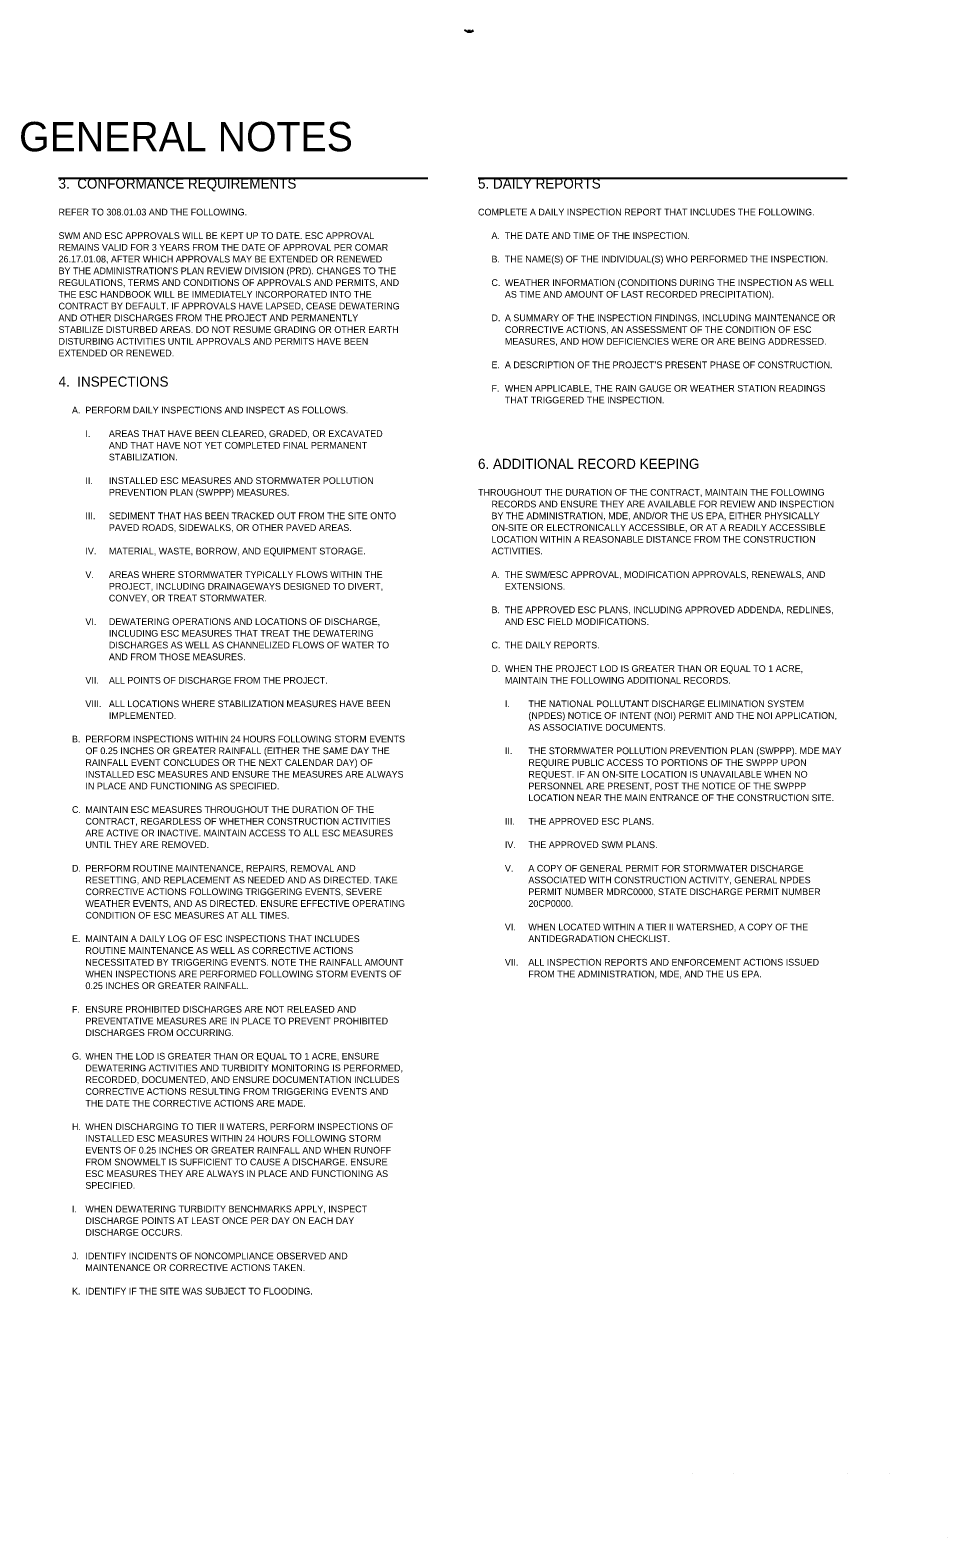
# Model space of a CAD drawing. Extents: x 1.3 to 34, y 0 to 22.5.
# Drawn here: x 20.33 to 34, y 0 to 22.46 of the extents above; entities that cross this region are included whole.
import ezdxf

# ---------------------------------------------------------------- set-up
doc = ezdxf.new("R2010")
doc.units = 0
for name, color, linetype in [('ANNO-NOTE', 7, 'Continuous'), ('TTLB-TEXT', 7, 'Continuous'), ('USER-LINE', 7, 'Continuous')]:
    doc.layers.add(name, color=color, linetype=linetype)

msp = doc.modelspace()

# ---------------------------------------------------------------- linework, layer by layer
at = {"layer": 'ANNO-NOTE'}
for p, q in [((26.891, 22.441), (26.93, 22.461)), ((26.891, 22.441), (26.93, 22.461)), ((26.891, 22.441), (26.93, 22.461)), ((26.843, 22.436), (26.799, 22.459)), ((26.843, 22.436), (26.799, 22.459)), ((26.843, 22.436), (26.799, 22.459)), ((26.843, 22.436), (26.894, 22.436)), ((26.843, 22.436), (26.894, 22.436)), ((26.843, 22.436), (26.894, 22.436)), ((26.844, 22.438), (26.892, 22.438)), ((26.844, 22.438), (26.892, 22.438)), ((26.844, 22.438), (26.892, 22.438)), ((26.845, 22.441), (26.891, 22.441)), ((26.845, 22.441), (26.891, 22.441)), ((26.845, 22.441), (26.891, 22.441)), ((26.847, 22.451), (26.89, 22.451)), ((26.847, 22.451), (26.89, 22.451)), ((26.847, 22.451), (26.89, 22.451)), ((26.847, 22.443), (26.89, 22.443)), ((26.847, 22.443), (26.89, 22.443)), ((26.847, 22.443), (26.89, 22.443)), ((26.848, 22.454), (26.888, 22.454)), ((26.848, 22.454), (26.888, 22.454)), ((26.848, 22.454), (26.888, 22.454)), ((26.848, 22.445), (26.889, 22.446)), ((26.848, 22.445), (26.889, 22.446)), ((26.848, 22.445), (26.889, 22.446)), ((26.892, 22.438), (26.931, 22.458)), ((26.892, 22.438), (26.931, 22.458)), ((26.892, 22.438), (26.931, 22.458)), ((26.894, 22.436), (26.932, 22.456)), ((26.894, 22.436), (26.932, 22.456)), ((26.894, 22.436), (26.932, 22.456))]:
    msp.add_line(p, q, dxfattribs=at)
at = {"layer": 'TTLB-TEXT'}
for p, q in [((30.191, 0.958), (30.191, 0.958)), ((30.807, 0.958), (30.807, 0.958)), ((32.512, 0.958), (32.512, 0.958)), ((33.128, 0.958), (33.128, 0.958))]:
    msp.add_line(p, q, dxfattribs=at)
at = {"layer": 'USER-LINE'}
for p, q in [((26.25, 20.25), (20.75, 20.25)), ((32.5, 20.25), (27, 20.25)), ((34, 0), (34, 0))]:
    msp.add_line(p, q, dxfattribs=at)

# ---------------------------------------------------------------- texts
at = {"layer": 'ANNO-NOTE'}
for s, height, p in [('EROSION AND SEDIMENT CONTROL (ESC) - GENERAL NOTES', 0.4375, (7.583, 20.656)), ('3.  CONFORMANCE REQUIREMENTS', 0.15, (20.75, 20.1)), ('5. DAILY REPORTS', 0.15, (27, 20.1)), ('REFER TO 308.01.03 AND THE FOLLOWING.', 0.1, (20.75, 19.7)), ('COMPLETE A DAILY INSPECTION REPORT THAT INCLUDES THE FOLLOWING.', 0.1, (27, 19.7)), ('SWM AND ESC APPROVALS WILL BE KEPT UP TO DATE. ESC APPROVAL ', 0.1, (20.75, 19.35)), ('A.', 0.1, (27.2, 19.35)), ('THE DATE AND TIME OF THE INSPECTION.', 0.1, (27.4, 19.35)), ('26.17.01.08, AFTER WHICH APPROVALS MAY BE EXTENDED OR RENEWED ', 0.1, (20.75, 19)), ('REMAINS VALID FOR 3 YEARS FROM THE DATE OF APPROVAL PER COMAR ', 0.1, (20.75, 19.175)), ('B.', 0.1, (27.2, 19)), ('THE NAME(S) OF THE INDIVIDUAL(S) WHO PERFORMED THE INSPECTION.', 0.1, (27.4, 19)), ('BY THE ADMINISTRATION’S PLAN REVIEW DIVISION (PRD). CHANGES TO THE ', 0.1, (20.75, 18.825)), ('REGULATIONS, TERMS AND CONDITIONS OF APPROVALS AND PERMITS, AND ', 0.1, (20.75, 18.65)), ('C.', 0.1, (27.2, 18.65)), ('WEATHER INFORMATION (CONDITIONS DURING THE INSPECTION AS WELL ', 0.1, (27.4, 18.65)), ('THE ESC HANDBOOK WILL BE IMMEDIATELY INCORPORATED INTO THE ', 0.1, (20.75, 18.475)), ('AS TIME AND AMOUNT OF LAST RECORDED PRECIPITATION).', 0.1, (27.4, 18.475)), ('AND OTHER DISCHARGES FROM THE PROJECT AND PERMANENTLY ', 0.1, (20.75, 18.125)), ('CONTRACT BY DEFAULT. IF APPROVALS HAVE LAPSED, CEASE DEWATERING ', 0.1, (20.75, 18.3)), ('D.', 0.1, (27.2, 18.125)), ('A SUMMARY OF THE INSPECTION FINDINGS, INCLUDING MAINTENANCE OR ', 0.1, (27.4, 18.125)), ('STABILIZE DISTURBED AREAS. DO NOT RESUME GRADING OR OTHER EARTH ', 0.1, (20.75, 17.95)), ('CORRECTIVE ACTIONS, AN ASSESSMENT OF THE CONDITION OF ESC ', 0.1, (27.4, 17.95)), ('DISTURBING ACTIVITIES UNTIL APPROVALS AND PERMITS HAVE BEEN ', 0.1, (20.75, 17.775)), ('MEASURES, AND HOW DEFICIENCIES WERE OR ARE BEING ADDRESSED.', 0.1, (27.4, 17.775)), ('EXTENDED OR RENEWED.', 0.1, (20.75, 17.6)), ('E.', 0.1, (27.2, 17.425)), ('A DESCRIPTION OF THE PROJECT’S PRESENT PHASE OF CONSTRUCTION.', 0.1, (27.4, 17.425)), ('4.  INSPECTIONS', 0.15, (20.75, 17.15)), ('F.', 0.1, (27.2, 17.075)), ('WHEN APPLICABLE, THE RAIN GAUGE OR WEATHER STATION READINGS ', 0.1, (27.4, 17.075)), ('A.', 0.1, (20.95, 16.75)), ('PERFORM DAILY INSPECTIONS AND INSPECT AS FOLLOWS.', 0.1, (21.15, 16.75)), ('THAT TRIGGERED THE INSPECTION.', 0.1, (27.4, 16.9)), ('I.', 0.1, (21.15, 16.4)), ('AREAS THAT HAVE BEEN CLEARED, GRADED, OR EXCAVATED ', 0.1, (21.5, 16.4)), ('AND THAT HAVE NOT YET COMPLETED FINAL PERMANENT ', 0.1, (21.5, 16.225)), ('STABILIZATION.', 0.1, (21.5, 16.05)), ('6. ADDITIONAL RECORD KEEPING', 0.15, (27, 15.925)), ('II.', 0.1, (21.15, 15.7)), ('INSTALLED ESC MEASURES AND STORMWATER POLLUTION ', 0.1, (21.5, 15.7)), ('PREVENTION PLAN (SWPPP) MEASURES.', 0.1, (21.5, 15.525)), ('THROUGHOUT THE DURATION OF THE CONTRACT, MAINTAIN THE FOLLOWING ', 0.1, (27, 15.525)), ('III.', 0.1, (21.15, 15.175)), ('SEDIMENT THAT HAS BEEN TRACKED OUT FROM THE SITE ONTO ', 0.1, (21.5, 15.175)), ('RECORDS AND ENSURE THEY ARE AVAILABLE FOR REVIEW AND INSPECTION ', 0.1, (27.2, 15.35)), ('BY THE ADMINISTRATION, MDE, AND/OR THE US EPA, EITHER PHYSICALLY ', 0.1, (27.2, 15.175)), ('PAVED ROADS, SIDEWALKS, OR OTHER PAVED AREAS.', 0.1, (21.5, 15)), ('ON-SITE OR ELECTRONICALLY ACCESSIBLE, OR AT A READILY ACCESSIBLE ', 0.1, (27.2, 15)), ('LOCATION WITHIN A REASONABLE DISTANCE FROM THE CONSTRUCTION ', 0.1, (27.2, 14.825)), ('IV.', 0.1, (21.15, 14.65)), ('MATERIAL, WASTE, BORROW, AND EQUIPMENT STORAGE.', 0.1, (21.5, 14.65)), ('ACTIVITIES.', 0.1, (27.2, 14.65)), ('V.', 0.1, (21.15, 14.3)), ('AREAS WHERE STORMWATER TYPICALLY FLOWS WITHIN THE ', 0.1, (21.5, 14.3)), ('A.', 0.1, (27.2, 14.3)), ('THE SWM/ESC APPROVAL, MODIFICATION APPROVALS, RENEWALS, AND ', 0.1, (27.4, 14.3)), ('PROJECT, INCLUDING DRAINAGEWAYS DESIGNED TO DIVERT, ', 0.1, (21.5, 14.125)), ('EXTENSIONS.', 0.1, (27.4, 14.125)), ('CONVEY, OR TREAT STORMWATER.', 0.1, (21.5, 13.95)), ('DEWATERING OPERATIONS AND LOCATIONS OF DISCHARGE, ', 0.1, (21.5, 13.6)), ('B.', 0.1, (27.2, 13.775)), ('AND ESC FIELD MODIFICATIONS.', 0.1, (27.4, 13.6)), ('THE APPROVED ESC PLANS, INCLUDING APPROVED ADDENDA, REDLINES, ', 0.1, (27.4, 13.775)), ('VI.', 0.1, (21.15, 13.6)), ('INCLUDING ESC MEASURES THAT TREAT THE DEWATERING ', 0.1, (21.5, 13.425)), ('DISCHARGES AS WELL AS CHANNELIZED FLOWS OF WATER TO ', 0.1, (21.5, 13.25)), ('C.', 0.1, (27.2, 13.25)), ('THE DAILY REPORTS.', 0.1, (27.4, 13.25)), ('AND FROM THOSE MEASURES.', 0.1, (21.5, 13.075)), ('VII.', 0.1, (21.15, 12.725)), ('ALL POINTS OF DISCHARGE FROM THE PROJECT.', 0.1, (21.5, 12.725)), ('D.', 0.1, (27.2, 12.9)), ('WHEN THE PROJECT LOD IS GREATER THAN OR EQUAL TO 1 ACRE, ', 0.1, (27.4, 12.9)), ('MAINTAIN THE FOLLOWING ADDITIONAL RECORDS.', 0.1, (27.4, 12.725)), ('VIII.', 0.1, (21.15, 12.375)), ('ALL LOCATIONS WHERE STABILIZATION MEASURES HAVE BEEN ', 0.1, (21.5, 12.375)), ('I.', 0.1, (27.4, 12.375)), ('THE NATIONAL POLLUTANT DISCHARGE ELIMINATION SYSTEM ', 0.1, (27.75, 12.375)), ('IMPLEMENTED.', 0.1, (21.5, 12.2)), ('(NPDES) NOTICE OF INTENT (NOI) PERMIT AND THE NOI APPLICATION, ', 0.1, (27.75, 12.2)), ('B.', 0.1, (20.95, 11.85)), ('PERFORM INSPECTIONS WITHIN 24 HOURS FOLLOWING STORM EVENTS ', 0.1, (21.15, 11.85)), ('AS ASSOCIATIVE DOCUMENTS.', 0.1, (27.75, 12.025)), ('OF 0.25 INCHES OR GREATER RAINFALL (EITHER THE SAME DAY THE ', 0.1, (21.15, 11.675)), ('II.', 0.1, (27.4, 11.675)), ('THE STORMWATER POLLUTION PREVENTION PLAN (SWPPP). MDE MAY ', 0.1, (27.75, 11.675)), ('RAINFALL EVENT CONCLUDES OR THE NEXT CALENDAR DAY) OF ', 0.1, (21.15, 11.5)), ('REQUIRE PUBLIC ACCESS TO PORTIONS OF THE SWPPP UPON ', 0.1, (27.75, 11.5)), ('INSTALLED ESC MEASURES AND ENSURE THE MEASURES ARE ALWAYS ', 0.1, (21.15, 11.325)), ('IN PLACE AND FUNCTIONING AS SPECIFIED.', 0.1, (21.15, 11.15)), ('REQUEST. IF AN ON-SITE LOCATION IS UNAVAILABLE WHEN NO ', 0.1, (27.75, 11.325)), ('PERSONNEL ARE PRESENT, POST THE NOTICE OF THE SWPPP ', 0.1, (27.75, 11.15)), ('LOCATION NEAR THE MAIN ENTRANCE OF THE CONSTRUCTION SITE.', 0.1, (27.75, 10.975)), ('C.', 0.1, (20.95, 10.8)), ('MAINTAIN ESC MEASURES THROUGHOUT THE DURATION OF THE ', 0.1, (21.15, 10.8)), ('CONTRACT, REGARDLESS OF WHETHER CONSTRUCTION ACTIVITIES ', 0.1, (21.15, 10.625)), ('III.', 0.1, (27.4, 10.625)), ('THE APPROVED ESC PLANS.', 0.1, (27.75, 10.625)), ('ARE ACTIVE OR INACTIVE. MAINTAIN ACCESS TO ALL ESC MEASURES ', 0.1, (21.15, 10.45)), ('UNTIL THEY ARE REMOVED.', 0.1, (21.15, 10.275)), ('IV.', 0.1, (27.4, 10.275)), ('THE APPROVED SWM PLANS.', 0.1, (27.75, 10.275)), ('D.', 0.1, (20.95, 9.925)), ('PERFORM ROUTINE MAINTENANCE, REPAIRS, REMOVAL AND ', 0.1, (21.15, 9.925)), ('V.', 0.1, (27.4, 9.925)), ('A COPY OF GENERAL PERMIT FOR STORMWATER DISCHARGE ', 0.1, (27.75, 9.925)), ('CORRECTIVE ACTIONS FOLLOWING TRIGGERING EVENTS, SEVERE ', 0.1, (21.15, 9.575)), ('RESETTING, AND REPLACEMENT AS NEEDED AND AS DIRECTED. TAKE ', 0.1, (21.15, 9.75)), ('ASSOCIATED WITH CONSTRUCTION ACTIVITY, GENERAL NPDES ', 0.1, (27.75, 9.75)), ('PERMIT NUMBER MDRC0000, STATE DISCHARGE PERMIT NUMBER ', 0.1, (27.75, 9.575)), ('WEATHER EVENTS, AND AS DIRECTED. ENSURE EFFECTIVE OPERATING ', 0.1, (21.15, 9.4)), ('20CP0000.', 0.1, (27.75, 9.4)), ('CONDITION OF ESC MEASURES AT ALL TIMES.', 0.1, (21.15, 9.225)), ('VI.', 0.1, (27.4, 9.05)), ('WHEN LOCATED WITHIN A TIER II WATERSHED, A COPY OF THE ', 0.1, (27.75, 9.05)), ('E.', 0.1, (20.95, 8.875)), ('MAINTAIN A DAILY LOG OF ESC INSPECTIONS THAT INCLUDES ', 0.1, (21.15, 8.875)), ('ROUTINE MAINTENANCE AS WELL AS CORRECTIVE ACTIONS ', 0.1, (21.15, 8.7)), ('ANTIDEGRADATION CHECKLIST.', 0.1, (27.75, 8.875)), ('NECESSITATED BY TRIGGERING EVENTS. NOTE THE RAINFALL AMOUNT ', 0.1, (21.15, 8.525)), ('VII.', 0.1, (27.4, 8.525)), ('ALL INSPECTION REPORTS AND ENFORCEMENT ACTIONS ISSUED ', 0.1, (27.75, 8.525)), ('WHEN INSPECTIONS ARE PERFORMED FOLLOWING STORM EVENTS OF ', 0.1, (21.15, 8.35)), ('FROM THE ADMINISTRATION, MDE, AND THE US EPA.', 0.1, (27.75, 8.35)), ('0.25 INCHES OR GREATER RAINFALL.', 0.1, (21.15, 8.175)), ('F.', 0.1, (20.95, 7.825)), ('ENSURE PROHIBITED DISCHARGES ARE NOT RELEASED AND ', 0.1, (21.15, 7.825)), ('PREVENTATIVE MEASURES ARE IN PLACE TO PREVENT PROHIBITED ', 0.1, (21.15, 7.65)), ('DISCHARGES FROM OCCURRING.', 0.1, (21.15, 7.475)), ('G.', 0.1, (20.95, 7.125)), ('WHEN THE LOD IS GREATER THAN OR EQUAL TO 1 ACRE, ENSURE ', 0.1, (21.15, 7.125)), ('DEWATERING ACTIVITIES AND TURBIDITY MONITORING IS PERFORMED, ', 0.1, (21.15, 6.95)), ('RECORDED, DOCUMENTED, AND ENSURE DOCUMENTATION INCLUDES ', 0.1, (21.15, 6.775)), ('THE DATE THE CORRECTIVE ACTIONS ARE MADE.', 0.1, (21.15, 6.425)), ('CORRECTIVE ACTIONS RESULTING FROM TRIGGERING EVENTS AND ', 0.1, (21.15, 6.6)), ('H.', 0.1, (20.95, 6.075)), ('WHEN DISCHARGING TO TIER II WATERS, PERFORM INSPECTIONS OF ', 0.1, (21.15, 6.075)), ('INSTALLED ESC MEASURES WITHIN 24 HOURS FOLLOWING STORM ', 0.1, (21.15, 5.9)), ('EVENTS OF 0.25 INCHES OR GREATER RAINFALL AND WHEN RUNOFF ', 0.1, (21.15, 5.725)), ('FROM SNOWMELT IS SUFFICIENT TO CAUSE A DISCHARGE. ENSURE ', 0.1, (21.15, 5.55)), ('ESC MEASURES THEY ARE ALWAYS IN PLACE AND FUNCTIONING AS ', 0.1, (21.15, 5.375)), ('SPECIFIED.', 0.1, (21.15, 5.2)), ('I.', 0.1, (20.95, 4.85)), ('WHEN DEWATERING TURBIDITY BENCHMARKS APPLY, INSPECT ', 0.1, (21.15, 4.85)), ('DISCHARGE POINTS AT LEAST ONCE PER DAY ON EACH DAY ', 0.1, (21.15, 4.675)), ('DISCHARGE OCCURS.', 0.1, (21.15, 4.5)), ('J.', 0.1, (20.95, 4.15)), ('MAINTENANCE OR CORRECTIVE ACTIONS TAKEN.', 0.1, (21.15, 3.975)), ('IDENTIFY INCIDENTS OF NONCOMPLIANCE OBSERVED AND ', 0.1, (21.15, 4.15)), ('K.', 0.1, (20.95, 3.625)), ('IDENTIFY IF THE SITE WAS SUBJECT TO FLOODING.', 0.1, (21.15, 3.625))]:
    msp.add_text(s, height=height, dxfattribs=at).set_placement(p)

doc.saveas('drawing.dxf')
